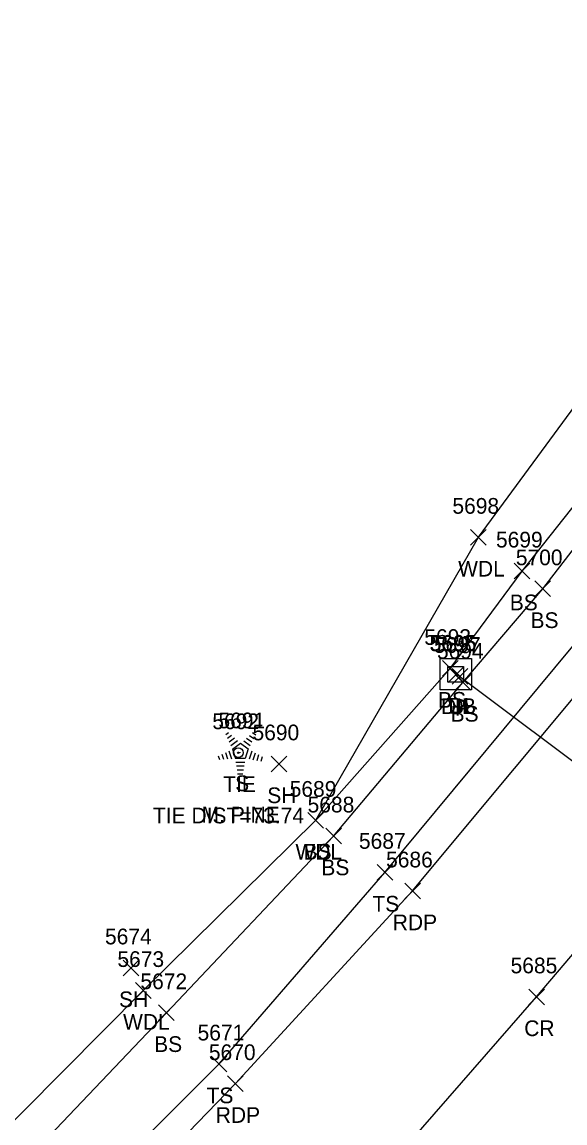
# Model space of a CAD drawing. Extents: x 1611797 to 1633212, y 298978 to 305475.
# Drawn here: x 1622412.2 to 1622481.4, y 301193 to 301333.3 of the extents above; entities that cross this region are included whole.
import ezdxf

# ---------------------------------------------------------------- set-up
doc = ezdxf.new("R2010")
doc.units = 0
for name, color, linetype in [('C_A', 7, 'Continuous'), ('C_C', 7, 'Continuous'), ('C_I', 7, 'Continuous'), ('CBP', 7, 'Continuous'), ('D_A', 7, 'Continuous'), ('D_I', 7, 'Continuous'), ('D_TIC', 7, 'Continuous'), ('DCP', 7, 'Continuous'), ('DS', 7, 'Continuous'), ('L_A', 7, 'Continuous'), ('L_C', 7, 'Continuous'), ('L_I', 7, 'Continuous'), ('L_TIC', 7, 'Continuous'), ('LAWA', 7, 'Continuous'), ('LELB', 7, 'Continuous'), ('LTC', 7, 'Continuous'), ('P_A', 7, 'Continuous'), ('P_I', 7, 'Continuous'), ('P_TIC', 7, 'Continuous'), ('PET', 7, 'Continuous'), ('PRC', 7, 'Continuous')]:
    doc.layers.add(name, color=color, linetype=linetype)

msp = doc.modelspace()

# ---------------------------------------------------------------- linework, layer by layer
at = {"layer": 'CBP'}
for radius in [0.625, 0.0833]:
    msp.add_circle((1622439.75, 301240.19), radius, dxfattribs=at)
at = {"layer": 'D_TIC'}
for points in [[(1622466.47, 301249.12), (1622468.47, 301251.12)], [(1622468.47, 301249.12), (1622466.47, 301251.12)], [(1622466.98, 301248.91), (1622468.98, 301250.91)], [(1622468.98, 301248.91), (1622466.98, 301250.91)]]:
    msp.add_lwpolyline(points, dxfattribs=at)
at = {"layer": 'DCP'}
msp.add_lwpolyline([(1622467.98, 301249.91), (1622542.05, 301194.41)], dxfattribs=at)
at = {"layer": 'DS'}
for p, q in [((1622465.45, 301252.18), (1622469.45, 301252.18)), ((1622465.45, 301248.18), (1622465.45, 301252.18)), ((1622469.45, 301252.18), (1622469.45, 301248.18)), ((1622466.45, 301249.18), (1622466.45, 301251.18)), ((1622466.45, 301251.18), (1622468.45, 301251.18)), ((1622468.45, 301251.18), (1622468.45, 301249.18)), ((1622468.45, 301249.18), (1622466.45, 301249.18)), ((1622467.45, 301250.18), (1622467.45, 301250.18)), ((1622467.45, 301250.18), (1622467.45, 301250.18)), ((1622469.45, 301248.18), (1622465.45, 301248.18))]:
    msp.add_line(p, q, dxfattribs=at)
at = {"layer": 'L_TIC'}
for points in [[(1622469.34, 301266.63), (1622471.34, 301268.63)], [(1622471.34, 301266.63), (1622469.34, 301268.63)], [(1622474.9, 301262.33), (1622476.9, 301264.33)], [(1622476.9, 301262.33), (1622474.9, 301264.33)], [(1622477.54, 301260.07), (1622479.54, 301262.07)], [(1622479.54, 301260.07), (1622477.54, 301262.07)], [(1622465.76, 301249.92), (1622467.76, 301251.92)], [(1622467.76, 301249.92), (1622465.76, 301251.92)], [(1622467.36, 301248.15), (1622469.36, 301250.15)], [(1622469.36, 301248.15), (1622467.36, 301250.15)], [(1622443.95, 301237.77), (1622445.95, 301239.77)], [(1622445.95, 301237.77), (1622443.95, 301239.77)], [(1622448.62, 301230.58), (1622450.62, 301232.58)], [(1622450.62, 301230.58), (1622448.62, 301232.58)], [(1622448.62, 301230.58), (1622450.62, 301232.58)], [(1622450.62, 301230.58), (1622448.62, 301232.58)], [(1622450.89, 301228.58), (1622452.89, 301230.58)], [(1622452.89, 301228.58), (1622450.89, 301230.58)], [(1622457.43, 301223.95), (1622459.43, 301225.95)], [(1622459.43, 301223.95), (1622457.43, 301225.95)], [(1622425.07, 301211.78), (1622427.07, 301213.78)], [(1622427.07, 301211.78), (1622425.07, 301213.78)], [(1622426.65, 301208.9), (1622428.65, 301210.9)], [(1622428.65, 301208.9), (1622426.65, 301210.9)], [(1622429.59, 301206.07), (1622431.59, 301208.07)], [(1622431.59, 301206.07), (1622429.59, 301208.07)], [(1622436.3, 301199.54), (1622438.3, 301201.54)], [(1622438.3, 301199.54), (1622436.3, 301201.54)]]:
    msp.add_lwpolyline(points, dxfattribs=at)
at = {"layer": 'LAWA'}
msp.add_lwpolyline([(1622387.76, 301179.05), (1622397.07, 301179.12), (1622427.65, 301209.9), (1622449.62, 301231.58), (1622470.34, 301267.63), (1622492.33, 301297.51), (1622515.41, 301331.49), (1622538.47, 301358.93), (1622560.23, 301389.57), (1622576.72, 301416.07), (1622576.44, 301420.03), (1622578.56, 301426.68), (1622588.66, 301437.97), (1622599.63, 301454.27), (1622615.5, 301489.08), (1622629.31, 301519.57), (1622648.55, 301554.37)], dxfattribs=at)
at = {"layer": 'LELB'}
for points in [[(1622303.98, 301104.59), (1622310.78, 301099.33), (1622319.48, 301096.25), (1622326.26, 301097.34), (1622347.55, 301114.38), (1622375.51, 301140.08), (1622405.76, 301169.1), (1622437.3, 301200.54), (1622458.43, 301224.95), (1622484.45, 301256.27), (1622508.57, 301286.02), (1622531.26, 301316.99), (1622553.65, 301348.32), (1622573.86, 301381.36), (1622587.24, 301406.84), (1622584.4, 301410.71), (1622576.72, 301416.07)], [(1622305.52, 301107.15), (1622315.07, 301105.99), (1622317.12, 301104.2), (1622343.27, 301121.96), (1622371.22, 301146.89), (1622399.94, 301174.87), (1622430.59, 301207.07), (1622451.89, 301229.58), (1622468.36, 301249.15), (1622478.54, 301261.07), (1622501.72, 301291.08), (1622524.3, 301323.22), (1622546.27, 301353.28), (1622567.71, 301385.93), (1622580.45, 301407.78)], [(1622449.62, 301231.58), (1622466.76, 301250.92), (1622475.9, 301263.33), (1622499.11, 301292.58), (1622520.81, 301325.55), (1622542.36, 301355.63), (1622564.75, 301388.23), (1622579.34, 301408.29), (1622580.45, 301407.78)]]:
    msp.add_lwpolyline(points, dxfattribs=at)
at = {"layer": 'LTC'}
for p, q in [((1622438.16, 301242.51), (1622438.51, 301242.77)), ((1622438.37, 301242.04), (1622438.89, 301242.43)), ((1622441.18, 301242.4), (1622441.73, 301242)), ((1622441.55, 301242.75), (1622441.97, 301242.45)), ((1622438.57, 301241.58), (1622439.28, 301242.09)), ((1622438.78, 301241.11), (1622439.66, 301241.75)), ((1622439.01, 301240.66), (1622440.02, 301241.39)), ((1622440.02, 301241.39), (1622441.02, 301240.67)), ((1622440.44, 301241.71), (1622441.25, 301241.12)), ((1622440.81, 301242.05), (1622441.49, 301241.56)), ((1622437.19, 301239.79), (1622437.34, 301239.32)), ((1622437.64, 301240.01), (1622437.86, 301239.35)), ((1622438.1, 301240.22), (1622438.37, 301239.39)), ((1622438.55, 301240.44), (1622438.89, 301239.42)), ((1622439.01, 301240.66), (1622439.4, 301239.46)), ((1622440.63, 301239.46), (1622439.4, 301239.46)), ((1622441.02, 301240.67), (1622440.63, 301239.46)), ((1622441.46, 301240.4), (1622441.12, 301239.36)), ((1622441.9, 301240.15), (1622441.61, 301239.26)), ((1622442.34, 301239.9), (1622442.11, 301239.17)), ((1622442.79, 301239.65), (1622442.6, 301239.07)), ((1622440.59, 301238.96), (1622439.44, 301238.96)), ((1622440.5, 301238.46), (1622439.52, 301238.46)), ((1622440.42, 301237.96), (1622439.59, 301237.96)), ((1622440.34, 301237.46), (1622439.66, 301237.46))]:
    msp.add_line(p, q, dxfattribs=at)
at = {"layer": 'P_TIC'}
for points in [[(1622460.95, 301221.58), (1622462.95, 301223.58)], [(1622462.95, 301221.58), (1622460.95, 301223.58)], [(1622476.75, 301208.09), (1622478.75, 301210.09)], [(1622478.75, 301208.09), (1622476.75, 301210.09)], [(1622438.39, 301197.04), (1622440.39, 301199.04)], [(1622440.39, 301197.04), (1622438.39, 301199.04)]]:
    msp.add_lwpolyline(points, dxfattribs=at)
at = {"layer": 'PET'}
msp.add_lwpolyline([(1622408.25, 301165.87), (1622439.39, 301198.04), (1622461.95, 301222.58), (1622487.93, 301253.76), (1622511.51, 301284.23), (1622534.35, 301314.53), (1622556.78, 301346.23), (1622577.91, 301378.88), (1622595.01, 301407.43), (1622603.73, 301423.2), (1622617.19, 301446.82), (1622634.21, 301479.77), (1622648.26, 301509.67), (1622665.21, 301547.65)], dxfattribs=at)
at = {"layer": 'PRC'}
msp.add_lwpolyline([(1622391.65, 301120.64), (1622424.38, 301151.76), (1622455.13, 301183.21), (1622477.75, 301209.09), (1622504, 301239.92), (1622528.25, 301271.13), (1622551.53, 301302.46), (1622573.96, 301335.04), (1622594.86, 301367.38), (1622615.3, 301401.53), (1622634.9, 301436.89), (1622652.67, 301471.55), (1622666.77, 301501.34), (1622684.44, 301540.78)], dxfattribs=at)

# ---------------------------------------------------------------- texts
at = {"layer": 'C_A'}
msp.add_text('TIE', height=2, dxfattribs=at).set_placement((1622437.82, 301235.19))
at = {"layer": 'C_C'}
msp.add_text('TIE DIST=73.74', height=2, dxfattribs=at).set_placement((1622428.88, 301231.19))
at = {"layer": 'C_I'}
msp.add_text('5692', height=2, dxfattribs=at).set_placement((1622436.44, 301243.19))
at = {"layer": 'D_A'}
for s, p in [('DIB', (1622465.58, 301245.12)), ('DI', (1622466.51, 301245.18)), ('P', (1622467.36, 301244.91))]:
    msp.add_text(s, height=2, dxfattribs=at).set_placement(p)
at = {"layer": 'D_I'}
for s, p in [('5696', (1622464.11, 301253.12)), ('5695', (1622464.15, 301253.18)), ('5697', (1622464.67, 301252.91))]:
    msp.add_text(s, height=2, dxfattribs=at).set_placement(p)
at = {"layer": 'L_A'}
for s, p in [('WDL', (1622467.76, 301262.63)), ('BS', (1622474.34, 301258.33)), ('BS', (1622476.98, 301256.07)), ('BS', (1622465.2, 301245.92)), ('BS', (1622466.8, 301244.15)), ('S', (1622439.35, 301235.3)), ('SH', (1622443.44, 301233.77)), ('WDL', (1622447.03, 301226.58)), ('BS', (1622448.06, 301226.58)), ('BS', (1622450.33, 301224.58)), ('TS', (1622456.84, 301219.95)), ('SH', (1622424.56, 301207.78)), ('WDL', (1622425.07, 301204.9)), ('BS', (1622429.03, 301202.07)), ('TS', (1622435.71, 301195.54))]:
    msp.add_text(s, height=2, dxfattribs=at).set_placement(p)
at = {"layer": 'L_C'}
msp.add_text('M. PINE', height=2, dxfattribs=at).set_placement((1622435.08, 301231.3))
at = {"layer": 'L_I'}
for s, p in [('5698', (1622467.03, 301270.63)), ('5699', (1622472.58, 301266.33)), ('5700', (1622475.11, 301264.07)), ('5693', (1622463.45, 301253.92)), ('5694', (1622465.06, 301252.15)), ('5691', (1622437.22, 301243.3)), ('5690', (1622441.56, 301241.77)), ('5689', (1622446.3, 301234.58)), ('5689', (1622446.3, 301234.58)), ('5688', (1622448.58, 301232.58)), ('5687', (1622455.12, 301227.95)), ('5674', (1622422.77, 301215.78)), ('5673', (1622424.35, 301212.9)), ('5672', (1622427.28, 301210.07)), ('5671', (1622434.56, 301203.54))]:
    msp.add_text(s, height=2, dxfattribs=at).set_placement(p)
at = {"layer": 'LTC'}
msp.add_text('.', height=1.04, rotation=270, dxfattribs=at).set_placement((1622439.9, 301240.41))
at = {"layer": 'P_A'}
for s, p in [('RDP', (1622459.43, 301217.58)), ('CR', (1622476.18, 301204.09)), ('RDP', (1622436.88, 301193.04))]:
    msp.add_text(s, height=2, dxfattribs=at).set_placement(p)
at = {"layer": 'P_I'}
for s, p in [('5686', (1622458.58, 301225.58)), ('5685', (1622474.44, 301212.09)), ('5670', (1622436, 301201.04))]:
    msp.add_text(s, height=2, dxfattribs=at).set_placement(p)

doc.saveas('drawing.dxf')
